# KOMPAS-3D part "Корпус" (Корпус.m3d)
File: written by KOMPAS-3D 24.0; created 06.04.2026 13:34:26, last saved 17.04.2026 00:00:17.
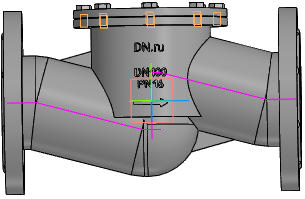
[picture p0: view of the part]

Document properties: Автор: R2D2; Полное имя файла: E:\Работа\Зайцев\VSO3131M-F-S Клапан запорный DN.ru Ду15-100 Ру16\DN100\исходные материалы\Корпус.m3d

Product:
- Body: Труба / Нестандартная труба / L = 174.4 мм  | qty 1
    Материал: Нестандартная труба (density 7856 kg/m3)
    Масса: 44.330468
    Раздел спецификации: Детали
    Примечание: 13,02 кг
    additional columns: Pipeline; 0.11; 0; 0; 0.002; 0.17439; true; 0.04
- Body: Труба / Нестандартная труба / L = 205.7 мм  | qty 1
    Материал: Нестандартная труба (density 7856 kg/m3)
    Масса: 44.330468
    Раздел спецификации: Детали
    Примечание: 15,36 кг
    additional columns: Pipeline; 0.11; 0; 0; 0.002; 0.20574; true; 0.04
- Body: Тело 4  | qty 1
    Материал: Нестандартная труба (density 7856 kg/m3)
    Масса: 44.330468
- Body: Тело 8  | qty 1
    Материал: Нестандартная труба (density 7856 kg/m3)
    Масса: 44.330468
- Body: Тело 9  | qty 1
    Материал: Нестандартная труба (density 7856 kg/m3)
    Масса: 44.330468
- Component [standard]: Hexagon head screw ISO 4017 - М10 x 20  | qty 8  | Масса: 0.023019; Рассекать на разрезах: no; source file: C:\Program Files\ASCON\KOMPAS-3D v24\Libs\PolynomLib\DATA\vault\Methods\Kompas\3D\PLib_Bolt_1_ISO_1100.m3d
- Part/product: Корпус
    Масса: 6.9

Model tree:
1. Труба
2. Труба:1  (labels: {F703FF30-5BE6-4673-A7F1-8EDA1BE1E2D1}; SHAPEOBJECT3D_ATTR_BUTT; SHAPEOBJECT3D_ATTR_VALID; SHAPEOBJECT3D_ATTR_BUTT_AREA)
     PIPE_R = 7
3. Труба:2  (labels: {F703FF30-5BE6-4673-A7F1-8EDA1BE1E2D1}; SHAPEOBJECT3D_ATTR_BUTT; SHAPEOBJECT3D_ATTR_VALID; SHAPEOBJECT3D_ATTR_BUTT_AREA)
     PIPE_R = 5
4. Колонна
5. Элемент выдавливания:1  (with: Грань.Операция без истории:1)  (labels: Клапан запорный DN.ru Ду100 Ру16)
     Смещение 2 = -5
6. Скругление:17  (with: Ребро.Элемент выдавливания:1)
     Радиус = 1
7. Скругление:18  (with: Ребро.Элемент выдавливания:1)
8. Скругление:24  (with: Ребро.Элемент выдавливания:1, Ребро.Скругление:18)
     Радиус = 2
9. Элемент выдавливания:2
     Расстояние 1 = 6
10. Эскиз:4  (with: Грань.Элемент выдавливания:1)
11. Элемент выдавливания:3
     Расстояние 1 = 17.5
12. Скругление:21  (with: Ребро.Элемент выдавливания:3)
13. ОТЛИВКА
14. Скругление:6  (with: Грань.Элемент выдавливания:1)
     Радиус = 2
15. Элемент выдавливания:6  (with: Грань.Элемент выдавливания:1)
     Смещение 1 = 4
16. ЛЕЙБЛ
17. Элемент выдавливания:7  (with: Грань.Элемент выдавливания:1)
     Расстояние 1 = 70.9917; Смещение 1 = 1
18. Фланец верх  (with: Ребро.Операция без истории:1)  (labels: Клапан запорный DN.ru Ду100 Ру16)
19. Элемент вращения:2
     Угол 1 = 360
20. Эскиз:12  (with: Грань.Элемент вращения:2)
21. Элемент выдавливания:9  (with: Грань.Элемент вращения:2)
     Расстояние 2 = 20
22. Массив по концентрической сетке:1  (with: Элемент выдавливания:9, Эскиз:12, Грань.Элемент вращения:2)  (8 pattern instances)
     Шаг 2 = 360
23. Фланец
24. Элемент вращения:1
     Угол 1 = 360
25. отвертие во фланце  (with: Грань.Элемент вращения:1)
26. Элемент выдавливания:8
27. Массив по концентрической сетке:2  (with: Элемент выдавливания:8, Эскиз:10, Грань.Элемент вращения:1)  (8 pattern instances)
     Шаг 2 = 360
28. Зеркальный массив:1
29. Экземпляр ( 1 )
30. Экземпляр ( 2 )  (with: Элемент вращения:1, Массив по концентрической сетке:2, Экземпляр ( 1 ), Элемент выдавливания:8)
31. Экземпляр ( 3 )  (with: Элемент выдавливания:8)
32. Экземпляр ( 4 )  (with: Элемент выдавливания:8)
33. Экземпляр ( 5 )  (with: Элемент выдавливания:8)
34. Экземпляр ( 6 )  (with: Элемент выдавливания:8)
35. Экземпляр ( 7 )  (with: Элемент выдавливания:8)
36. Экземпляр ( 8 )  (with: Элемент выдавливания:8)
37. Скругление:26  (with: Ребро.Элемент выдавливания:1, Массив по концентрической сетке:1, Грань.Элемент вращения:2)  (labels: Грань.Элемент выдавливания:9.Экземпляр ( 1, 3 ))  (8 pattern instances)
     Радиус = 2; N 1 = 1; Шаг 1 = 10; Шаг 2 = 360; Номер 1 = 1

Expressions: DS/2+3; DN/2; D/2; DS-v977*4; LL/2; D1-v1234*2
Referenced files in C:\Program Files\ASCON\KOMPAS-3D v24\Libs\Pipeline\: StylesTemplate.a3d, TemplateHPH, InsulationStylesTemplate.a3d, Insulation
Referenced files in C:\Program Files\ASCON\KOMPAS-3D v24\Templates\: Констр. чертеж А3 гориз. перв. лист.cdt
Referenced files in E:\Работа\Зайцев\VSO3131M-F-S Клапан запорный DN.ru Ду15-100 Ру40\DN20\исходные материалы\: 
Referenced files in C:\Program Files\ASCON\KOMPAS-3D v24\Libs\PolynomLib\DATA\vault\Methods\Kompas\3D\: PLib_Bolt_1_ISO_1100.m3d
Referenced files in E:\Работа\Зайцев\VSO3131M-F-S Клапан запорный DN.ru Ду15-100 Ру16\DN100\исходные материалы\: VSO3131M-F-S Клапан запорный DN.ru Ду100 Ру16.a3d
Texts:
  Отводы ГОСТ 17375-2001
  Констр. чертеж А3 гориз. перв. лист.cdt
  BOSimple***PART:c031cb5e-65ec-2f83-1ced-75228c8ad34f***PART:A259_7B16EF33AB1642D2[16;1,5;20;10;-;Undefined]
  GOST 26.020 Pr3
  var3D
  смещение колонны вниз
  LL-10
  DN+10
  Hexagon head screw ISO 4017 - М10 x 20 (1)
  hole1
  hole2
  Труба / Нестандартная труба / L = %s мм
